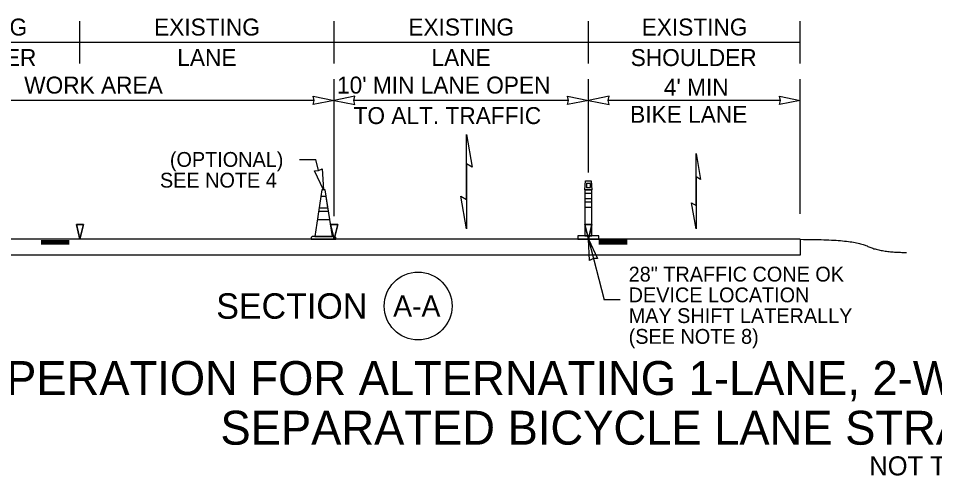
# Model space of a CAD drawing. Extents: x 99999.1 to 100095.7, y 99995 to 100010.7.
# Drawn here: x 100045 to 100049.325, y 100001.18 to 100003.339 of the extents above; entities that cross this region are included whole.
import ezdxf

# ---------------------------------------------------------------- set-up
doc = ezdxf.new("R2010")
doc.units = 0
for name, color, linetype in [('SH_DE_DetailHeading1Text', 7, 'Continuous'), ('TR_WZ_TrafficConeElev', 7, 'Continuous'), ('TR_WZ_TubularMarkerElev', 7, 'Continuous'), ('TR_WZ_WorkZoneDetails', 7, 'Continuous'), ('TR_WZ_WorkZoneTextCurrent', 7, 'Continuous')]:
    doc.layers.add(name, color=color, linetype=linetype)

msp = doc.modelspace()

# ---------------------------------------------------------------- linework, layer by layer
at = {"layer": 'TR_WZ_TrafficConeElev'}
for p, q in [((100046.4282, 100002.4976), (100046.4199, 100002.4434)), ((100046.4534, 100002.4976), (100046.4282, 100002.4976)), ((100046.4617, 100002.4434), (100046.4534, 100002.4976)), ((100046.4173, 100002.4268), (100046.4116, 100002.3893)), ((100046.4642, 100002.4268), (100046.4173, 100002.4268)), ((100046.4199, 100002.4434), (100046.4617, 100002.4434)), ((100046.47, 100002.3893), (100046.4642, 100002.4268)), ((100046.4116, 100002.3893), (100046.47, 100002.3893)), ((100046.3871, 100002.308), (100046.383, 100002.3038)), ((100046.383, 100002.3038), (100046.383, 100002.2955)), ((100046.383, 100002.2955), (100046.4986, 100002.2955)), ((100046.3991, 100002.308), (100046.3871, 100002.308)), ((100046.4986, 100002.3038), (100046.4944, 100002.308)), ((100046.4986, 100002.2955), (100046.4986, 100002.3038))]:
    msp.add_line(p, q, dxfattribs=at)
msp.add_lwpolyline([(100046.3991, 100002.308), (100046.4824, 100002.308), (100046.4486, 100002.5288), (100046.433, 100002.5288)], close=True, dxfattribs=at)
msp.add_lwpolyline([(100046.3991, 100002.308), (100046.4824, 100002.308), (100046.4486, 100002.5288), (100046.433, 100002.5288)], close=True, dxfattribs=at)
msp.add_lwpolyline([(100046.4944, 100002.308), (100046.4824, 100002.308), (100046.3991, 100002.308)], dxfattribs=at)
at = {"layer": 'TR_WZ_TubularMarkerElev'}
for p, q in [((100047.6824, 100002.5612), (100047.6998, 100002.5612)), ((100047.7074, 100002.5125), (100047.6741, 100002.5125)), ((100047.6741, 100002.5125), (100047.6741, 100002.4879)), ((100047.6743, 100002.5288), (100047.7072, 100002.5288)), ((100047.6998, 100002.539), (100047.6824, 100002.539)), ((100047.7074, 100002.4879), (100047.7074, 100002.5125)), ((100047.6741, 100002.4879), (100047.7074, 100002.4879)), ((100047.6741, 100002.4715), (100047.6741, 100002.447)), ((100047.7074, 100002.4715), (100047.6741, 100002.4715)), ((100047.7074, 100002.447), (100047.7074, 100002.4715)), ((100047.6741, 100002.447), (100047.7074, 100002.447)), ((100047.6408, 100002.3119), (100047.6408, 100002.2955)), ((100047.6408, 100002.2955), (100047.7408, 100002.2955)), ((100047.7408, 100002.2955), (100047.7408, 100002.3119))]:
    msp.add_line(p, q, dxfattribs=at)
msp.add_lwpolyline([(100047.6743, 100002.5288), (100047.6774, 100002.5713), (100047.7044, 100002.5713), (100047.7072, 100002.5288)], close=True, dxfattribs=at)
for points in [[(100047.6741, 100002.3119), (100047.7074, 100002.3119), (100047.7074, 100002.5247)], [(100047.6741, 100002.5247), (100047.6741, 100002.3119)], [(100047.6741, 100002.3119), (100047.7074, 100002.3119), (100047.7074, 100002.5247)], [(100047.6741, 100002.5247), (100047.6741, 100002.3119)], [(100047.7072, 100002.5288), (100047.6743, 100002.5288), (100047.7072, 100002.5288), (100047.6743, 100002.5288)], [(100047.7072, 100002.5288), (100047.6743, 100002.5288), (100047.7072, 100002.5288), (100047.6743, 100002.5288)], [(100047.7408, 100002.3119), (100047.7074, 100002.3119), (100047.6741, 100002.3119), (100047.6408, 100002.3119)]]:
    msp.add_lwpolyline(points, dxfattribs=at)
for centre, major_axis, ratio, start_param, end_param in [((100047.6824, 100002.5501), (0, 0.0111), 0.071484, 0, 3.141593), ((100047.6998, 100002.5501), (0, 0.0111), 0.071484, 3.141593, 6.283185), ((100047.6744, 100002.5238), (0, 0.00512), 0.053405, 0.177149, 1.393647), ((100047.6744, 100002.5238), (0, 0.00512), 0.053405, 0.177149, 1.393647), ((100047.7072, 100002.5238), (0, 0.00512), 0.053405, 4.889538, 6.106036), ((100047.7072, 100002.5238), (0, 0.00512), 0.053405, 4.889538, 6.106036)]:
    msp.add_ellipse(centre, major_axis=major_axis, ratio=ratio, start_param=start_param, end_param=end_param, dxfattribs=at)
at = {"layer": 'TR_WZ_WorkZoneDetails'}
for p, q in [((100045.2907, 100003.1255), (100045.2907, 100003.3255)), ((100046.4907, 100003.1255), (100046.4907, 100003.3255)), ((100047.6907, 100003.1255), (100047.6907, 100003.3255)), ((100048.6907, 100003.1255), (100048.6907, 100003.3255)), ((100044.2907, 100003.2255), (100045.2907, 100003.2255)), ((100045.2907, 100003.2255), (100046.4907, 100003.2255)), ((100046.4907, 100003.2255), (100047.6907, 100003.2255)), ((100047.6907, 100003.2255), (100048.6907, 100003.2255)), ((100046.4907, 100002.4052), (100046.4907, 100003.0515)), ((100047.6907, 100002.6113), (100047.6907, 100003.0515)), ((100048.6907, 100002.4152), (100048.6907, 100003.0515)), ((100046.397, 100002.9515), (100044.3844, 100002.9515)), ((100047.5969, 100002.9515), (100046.5844, 100002.9515)), ((100048.597, 100002.9515), (100047.7844, 100002.9515)), ((100046.3275, 100002.6715), (100046.4037, 100002.6715)), ((100046.4172, 100002.6196), (100046.4037, 100002.6715)), ((100047.1157, 100002.6519), (100047.1157, 100002.4831)), ((100047.1157, 100002.4831), (100047.1157, 100002.6519)), ((100048.199, 100002.5906), (100048.199, 100002.4555)), ((100048.199, 100002.4555), (100048.199, 100002.5906)), ((100048.6907, 100002.2954), (100044.2907, 100002.2954)), ((100047.6907, 100002.2954), (100047.7647, 100002.0101)), ((100048.6907, 100002.2954), (100048.6907, 100002.2204)), ((100045.1077, 100002.2902), (100045.2407, 100002.2902)), ((100045.1077, 100002.2846), (100045.2407, 100002.2846)), ((100045.1077, 100002.2789), (100045.2407, 100002.2789)), ((100045.1077, 100002.2737), (100045.2407, 100002.2737)), ((100047.8737, 100002.2898), (100047.7407, 100002.2898)), ((100047.8737, 100002.2842), (100047.7407, 100002.2842)), ((100047.8737, 100002.2785), (100047.7407, 100002.2785)), ((100047.8737, 100002.2733), (100047.7407, 100002.2733)), ((100048.6907, 100002.2204), (100044.2907, 100002.2204)), ((100047.841, 100002.0101), (100047.7647, 100002.0101))]:
    msp.add_line(p, q, dxfattribs=at)
for points in [[(100046.4907, 100002.9515), (100046.3924, 100002.9322), (100046.397, 100002.9515), (100046.3924, 100002.9708)], [(100046.4907, 100002.9515), (100046.589, 100002.9322), (100046.5844, 100002.9515), (100046.589, 100002.9708)], [(100047.6907, 100002.9515), (100047.5924, 100002.9322), (100047.5969, 100002.9515), (100047.5924, 100002.9708)], [(100047.6907, 100002.9515), (100047.7889, 100002.9322), (100047.7844, 100002.9515), (100047.7889, 100002.9708)], [(100048.6907, 100002.9515), (100048.5924, 100002.9322), (100048.597, 100002.9515), (100048.5924, 100002.9708)], [(100047.1157, 100002.7895), (100047.1427, 100002.6363), (100047.1157, 100002.6519)], [(100048.199, 100002.7007), (100048.2206, 100002.5781), (100048.199, 100002.5906)], [(100046.4408, 100002.5288), (100046.3975, 100002.6192), (100046.4173, 100002.6196), (100046.4348, 100002.6288)], [(100047.1157, 100002.3454), (100047.0887, 100002.4987), (100047.1157, 100002.4831)], [(100048.199, 100002.3454), (100048.1774, 100002.468), (100048.199, 100002.4555)], [(100045.2907, 100002.2954), (100045.274, 100002.3652), (100045.3073, 100002.3652)], [(100046.4907, 100002.2954), (100046.474, 100002.3652), (100046.5074, 100002.3652)], [(100047.6907, 100002.2954), (100047.674, 100002.3652), (100047.7073, 100002.3652)], [(100047.6907, 100002.2954), (100047.734, 100002.2051), (100047.7142, 100002.2047), (100047.6967, 100002.1955)]]:
    msp.add_lwpolyline(points, close=True, dxfattribs=at)
for points in [[(100045.3073, 100002.3652), (100045.274, 100002.3652), (100045.2907, 100002.2954), (100045.3073, 100002.3652)], [(100046.5074, 100002.3652), (100046.474, 100002.3652), (100046.4907, 100002.2954), (100046.5074, 100002.3652)], [(100047.7073, 100002.3652), (100047.674, 100002.3652), (100047.6907, 100002.2954), (100047.7073, 100002.3652)]]:
    msp.add_lwpolyline(points, dxfattribs=at)
msp.add_circle((100046.8872, 100001.9805), 0.16, dxfattribs=at)
msp.add_open_spline([(100048.6907, 100002.2954), (100048.9419, 100002.2956), (100049.0674, 100002.2335), (100049.1928, 100002.2336)], degree=2, dxfattribs=at)

# ---------------------------------------------------------------- texts
at = {"layer": 'SH_DE_DetailHeading1Text'}
for s, height, p in [('PILOT CAR OPERATION FOR ALTERNATING 1-LANE, 2-WAY TRAFFIC: AFAD-CONTROLLED + TEMP. RUMBLE STRIPS', 0.16, (100043.5871, 100001.5606)), ('SEPARATED BICYCLE LANE STRATEGY (45+ MPH HIGHWAYS)', 0.16, (100045.9541, 100001.3259)), ('NOT TO SCALE', 0.09, (100049.0168, 100001.1809))]:
    msp.add_text(s, height=height, rotation=360, dxfattribs=at).set_placement(p)
at = {"layer": 'TR_WZ_WorkZoneDetails'}
for s, height, p in [('EXISTING', 0.08, (100044.5424, 100003.2575)), ('EXISTING', 0.08, (100045.6409, 100003.2575)), ('EXISTING', 0.08, (100046.8409, 100003.2575)), ('EXISTING', 0.08, (100047.9424, 100003.2575)), ('SHOULDER', 0.08, (100044.4905, 100003.1135)), ('LANE', 0.08, (100045.7503, 100003.1135)), ('LANE', 0.08, (100046.9503, 100003.1135)), ('SHOULDER', 0.08, (100047.8905, 100003.1135)), ('SECTION', 0.12, (100045.9342, 100001.9205)), ('A-A', 0.1, (100046.7694, 100001.9305))]:
    msp.add_text(s, height=height, rotation=360, dxfattribs=at).set_placement(p)
for s, p in [('WORK AREA', (100045.0278, 100002.9835)), ("10' MIN LANE OPEN", (100046.5043, 100002.9835)), ("4' MIN", (100048.0471, 100002.9735)), ('TO ALT. TRAFFIC', (100046.5824, 100002.8395)), ('BIKE LANE', (100047.8881, 100002.8455))]:
    msp.add_text(s, height=0.08, dxfattribs=at).set_placement(p)
at = {"layer": 'TR_WZ_WorkZoneTextCurrent'}
for s, p in [('(OPTIONAL)', (100045.7154, 100002.6375)), ('SEE NOTE 4', (100045.6685, 100002.5395)), ('28" TRAFFIC CONE OK', (100047.881, 100002.0961)), ('DEVICE LOCATION', (100047.881, 100001.9981)), ('MAY SHIFT LATERALLY ', (100047.881, 100001.9001)), ('(SEE NOTE 8)', (100047.881, 100001.8021))]:
    msp.add_text(s, height=0.07, dxfattribs=at).set_placement(p)

doc.saveas('drawing.dxf')
